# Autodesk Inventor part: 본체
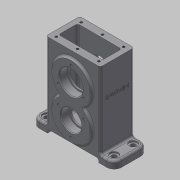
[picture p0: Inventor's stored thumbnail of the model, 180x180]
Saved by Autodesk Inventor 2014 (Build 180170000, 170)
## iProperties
Created: 2020-03
Part Number: 본체
Material: 일반
Document SubType Name: Modeling
Designer: mduedu
Density: 1 g/cm^3
Appearance: 기본값
Mass: 220.307 g
Surface Area: 576.062 cm^2
Volume: 220.307 cm^3
Author: mduedu
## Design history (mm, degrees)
sketch "스케치1"
  geometry: L1 (-56, 0)-(56, 0); L2 (56, 0)-(56, 10); L3 (-56, 10)-(-56, 0); L4 (37, 10)-(37, 114); L5 (37, 114)-(-37, 114); L6 (-37, 114)-(-37, 10); L7 (56, 10)-(37, 10); L8 (-37, 10)-(-56, 10); L9 (0, 0)-(0, 114); 1 further point
  constraints: 18 end point, 5 parallel, 2 midpoint, 2 vertical, 1 coincident, 1 horizontal, 1 perpendicular
  dimensions: "d0" = 112 distance of L1.start L1.end; "d2" = 10 distance of L1.end L2.end; "d3" = 114 distance between parallel lines of L5 L1; "d4" = 74 distance between parallel lines of L4 L6
extrude "돌출1" new body sketch "스케치1" stored distance "d5" = 46; taper "d6" = 0 deg
sketch "스케치2"
  geometry: L1 (56, 0)-(-56, 0) reference; C1 r 26 at (0, 34); C2 r 26 at (0, 79); 1 further point
  constraints: 2 centre point, 2 vertical alignment, 1 equal radius
  dimensions: "d7" = 52 diameter of C2; "d9" = 34 distance from line of C1.centre L1; "d10" = 45 distance of C2.centre C1.centre
extrude "돌출2" join sketch "스케치2" stored distance "d11" = 52; taper "d12" = 0 deg
fillet "모깎기1" dims "d13" = 3
fillet "모깎기2" dims "d14" = 3
fillet "모깎기3" dims "d15" = 10
fillet "모깎기4" dims "d16" = 3
fillet "모깎기5" dims "d17" = 3
sketch "스케치3"
  geometry: L1 (-30, 114)-(30, 114); L2 (30, 114)-(30, 13); L3 (30, 13)-(-30, 13); L4 (-30, 13)-(-30, 114); L5 (-34, 114)-(34, 114) reference; L6 (46, 0)-(-46, 0) reference; 2 further points
  constraints: 8 end point, 2 parallel, 1 collinear, 1 horizontal, 1 midpoint, 1 perpendicular, 1 vertical alignment
  dimensions: "d18" = 60 distance between parallel lines of L2 L4; "d20" = 13 distance between parallel lines of L3 L6
extrude "돌출3" cut sketch "스케치3" stored distance "d21" = 26; taper "d22" = 0 deg
fillet "모깎기6" dims "d23" = 3
fillet "모깎기7" dims "d24" = 3
sketch "스케치4"
  geometry: L1 (-35, 0)-(35, 0); L2 (35, 0)-(35, 5); L3 (35, 5)-(-35, 5); L4 (-35, 5)-(-35, 0); 2 further points
  constraints: 8 end point, 2 parallel, 1 coincident, 1 horizontal, 1 midpoint, 1 perpendicular
  dimensions: "d25" = 70 distance of L1.start L1.end; "d27" = 5 distance of L1.end L2.end
extrude "돌출4" cut sketch "스케치4" stored distance "d28" = 26; taper "d29" = 0 deg
fillet "모깎기8" dims "d30" = 3
sketch "스케치5"
  geometry: A1 r 10 centre (-86, 33) between (-86, 43) and (-96, 33) reference; A2 r 10 centre (-86, 7) between (-96, 7) and (-86, -3) reference; A3 r 10 centre (6, 7) between (6, -3) and (16, 7) reference; A4 r 10 centre (6, 33) between (16, 33) and (6, 43) reference; 5 further points
  constraints: 4 coincident
hole "구멍1" sketch "스케치5" at (-86, 33), (-86, 7), (6, 7), (6, 33) diameter "d31" = 6.6; stored, may be unused: countersink angle "d35" = 90 deg, drill point angle "d37" = 118 deg; dims "d32" = 6, "d33" = 11, "d34" = 2, "d36" = 8
sketch "스케치6"
  geometry: A1 r 26 centre (0, 34) between (-16.403, 54.172) and (16.403, 54.172) reference; A2 r 3 centre (18.296, 56.5) between (16.403, 58.828) and (16.403, 54.172) reference; A3 r 26 centre (0, 79) between (16.403, 58.828) and (-16.403, 58.828) reference; A4 r 3 centre (-18.296, 56.5) between (-16.403, 54.172) and (-16.403, 58.828) reference; 2 further points
  constraints: 1 coincident
hole "구멍2" sketch "스케치6" at (0, 79) diameter "d38" = 28; stored, may be unused: countersink angle "d42" = 90 deg, drill point angle "d44" = 118 deg; dims "d39" = 6, "d40" = 32, "d41" = 11, "d43" = 8
sketch "스케치7"
  geometry: C1 r 16 at (0, 79) reference; A1 r 26 centre (0, 34) between (-16.403, 54.172) and (16.403, 54.172) reference; A2 r 3 centre (18.296, 56.5) between (16.403, 58.828) and (16.403, 54.172) reference; A3 r 26 centre (0, 79) between (16.403, 58.828) and (-16.403, 58.828) reference; A4 r 3 centre (-18.296, 56.5) between (-16.403, 54.172) and (-16.403, 58.828) reference; 2 further points
  constraints: 1 coincident
hole "구멍3" sketch "스케치7" at (0, 34) diameter "d45" = 24; stored, may be unused: countersink angle "d49" = 90 deg, drill point angle "d51" = 118 deg; dims "d46" = 6, "d47" = 28, "d48" = 11, "d50" = 8
sketch "스케치8"
  geometry: C1 r 14 at (0, 34) reference; A1 r 26 centre (0, 34) between (-16.403, 54.172) and (16.403, 54.172) reference; A2 r 3 centre (18.296, 56.5) between (16.403, 58.828) and (16.403, 54.172) reference; A3 r 26 centre (0, 79) between (16.403, 58.828) and (-16.403, 58.828) reference; A4 r 3 centre (-18.296, 56.5) between (-16.403, 54.172) and (-16.403, 58.828) reference; 2 further points
  constraints: 1 coincident
hole "구멍4" sketch "스케치8" at (0, 79) diameter "d52" = 24; stored, may be unused: countersink angle "d56" = 90 deg, drill point angle "d58" = 118 deg; dims "d53" = 6, "d54" = 28, "d55" = 11, "d57" = 8
sketch "스케치9" dims "d59" = 40
  geometry: C1 r 14 at (0, 34) reference; C2 r 16 at (0, 79) reference; A1 r 26 centre (0, 34) between (-16.403, 54.172) and (16.403, 54.172) reference; A2 r 3 centre (18.296, 56.5) between (16.403, 58.828) and (16.403, 54.172) reference; A3 r 26 centre (0, 79) between (16.403, 58.828) and (-16.403, 58.828) reference; A4 r 3 centre (-18.296, 56.5) between (-16.403, 54.172) and (-16.403, 58.828) reference; 3 further points
  constraints: 2 vertical alignment, 1 coincident, 2 other
hole "구멍5" sketch "스케치9" at (0, 99) diameter "d61" = 3.242; stored, may be unused: countersink angle "d65" = 90 deg, drill point angle "d67" = 118 deg; dims "d62" = 8, "d63" = 28, "d64" = 11, "d66" = 10
sketch "스케치10" dims "d71" = 40
  geometry: C1 r 1.621 at (17.321, 69) reference; C2 r 1.621 at (-17.321, 69) reference; C3 r 1.621 at (0, 99) reference; C4 r 14 at (0, 34) reference; C5 r 16 at (0, 79) reference; A1 r 26 centre (0, 34) between (-16.403, 54.172) and (16.403, 54.172) reference; A2 r 3 centre (18.296, 56.5) between (16.403, 58.828) and (16.403, 54.172) reference; A3 r 26 centre (0, 79) between (16.403, 58.828) and (-16.403, 58.828) reference; A4 r 3 centre (-18.296, 56.5) between (-16.403, 54.172) and (-16.403, 58.828) reference; 3 further points
  constraints: 2 vertical alignment, 1 coincident, 2 other
hole "구멍6" sketch "스케치10" at (0, 14) diameter "d72" = 3.242; stored, may be unused: countersink angle "d76" = 90 deg, drill point angle "d78" = 118 deg; dims "d73" = 8, "d74" = 28, "d75" = 11, "d77" = 10
sketch "스케치11"
  geometry: L1 (5, 6)-(63, 6); L2 (63, 6)-(63, 40); L3 (63, 40)-(5, 40); L4 (5, 40)-(5, 6); L5 (5, 6)-(63, 40); L6 (63, 6)-(5, 40); 7 further points
  constraints: 12 end point, 4 coincident, 4 midpoint, 2 parallel, 1 horizontal, 1 perpendicular
  dimensions: "d82" = 58 distance of L3.end L2.end; "d83" = 34 distance of L2.end L1.end
hole "구멍7" sketch "스케치11" at (5, 40), (63, 40), (63, 6), (5, 6), (34, 6), (34, 40) diameter "d84" = 3.242; stored, may be unused: countersink angle "d88" = 90 deg, drill point angle "d90" = 118 deg; dims "d85" = 8, "d86" = 28, "d87" = 11, "d89" = 10
fillet "모깎기9" dims "d91" = 0.3
chamfer "모따기1" distance "d92" = 1; stored, may be unused: second distance "d93" = 2, angle "d94" = 45 deg
sketch "스케치12"
  geometry: 2 further points
  constraints: 1 coincident
hole "구멍8" sketch "스케치12" at (0, -23) diameter "d95" = 4.917; stored, may be unused: countersink angle "d99" = 90 deg, drill point angle "d101" = 118 deg; dims "d96" = 8, "d97" = 12, "d98" = 1, "d100" = 10
sketch "스케치13"
  geometry: L1 (33, -13)-(7, -13) reference; L2 (40, 101)-(0, 101) reference; 3 further points
  constraints: 1 midpoint, 1 vertical alignment, 1 other
  dimensions: "d102" = 40 distance from line of point (20, 61) L2
feature "엠보싱1" sketch "스케치13" dims "d0" = 112, "d2" = 10, "d3" = 114, "d4" = 74, "d13" = 3, "d103" = 0.5, "d104" = 0
node "솔리드1"
mirror "대칭1"
pattern_circular "원형 패턴1" dims angle "d69" = 360 deg
pattern_circular "원형 패턴2" dims angle "d80" = 360 deg
mirror "대칭2"
node "투영된 루프1"
node "투영된 루프2"
node "투영된 루프3"
node "투영된 루프4"
node "투영된 루프5"
